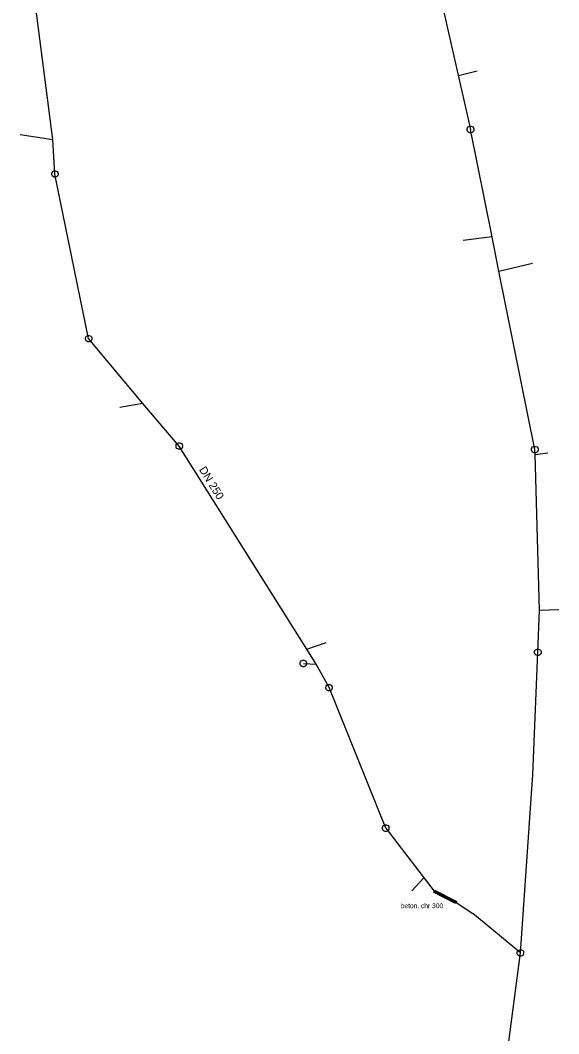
# Model space of a CAD drawing. Extents: x -717256 to -716843, y -1145423 to -1142840.
# Drawn here: x -717074.8 to -716990.8, y -1143505.2 to -1143346.8 of the extents above; entities that cross this region are included whole.
import ezdxf

# ---------------------------------------------------------------- set-up
doc = ezdxf.new("R2010")
doc.units = 0
for name, color, linetype in [('Vrstva 29', 7, 'Continuous'), ('Vrstva 30', 7, 'Continuous'), ('Vrstva 31', 7, 'Continuous')]:
    doc.layers.add(name, color=color, linetype=linetype)

msp = doc.modelspace()

# ---------------------------------------------------------------- linework, layer by layer
at = {"layer": 'Vrstva 29'}
for p, q in [((-717006.857, -1143484.87), (-717010.323, -1143483.098)), ((-717010.14, -1143482.741), (-717006.674, -1143484.513))]:
    msp.add_line(p, q, dxfattribs=at)
at = {"layer": 'Vrstva 30'}
for p, q in [((-717010.994, -1143335.446), (-717004.534, -1143363.907)), ((-717069.755, -1143365.449), (-717073.23, -1143338.352)), ((-717005.034, -1143363.807), (-717004.984, -1143363.657)), ((-717005.034, -1143364.007), (-717005.034, -1143363.807)), ((-717004.934, -1143364.257), (-717005.034, -1143364.007)), ((-717004.984, -1143363.657), (-717004.884, -1143363.507)), ((-717004.784, -1143364.357), (-717004.934, -1143364.257)), ((-717004.884, -1143363.507), (-717004.634, -1143363.407)), ((-717004.634, -1143364.407), (-717004.784, -1143364.357)), ((-717004.634, -1143363.407), (-717004.434, -1143363.407)), ((-717004.434, -1143364.407), (-717004.634, -1143364.407)), ((-717001.163, -1143380.697), (-717004.534, -1143363.907)), ((-717004.434, -1143363.407), (-717004.184, -1143363.507)), ((-717004.284, -1143364.357), (-717004.434, -1143364.407)), ((-717004.134, -1143364.257), (-717004.284, -1143364.357)), ((-717004.184, -1143363.507), (-717004.084, -1143363.657)), ((-717004.034, -1143364.007), (-717004.134, -1143364.257)), ((-717004.084, -1143363.657), (-717004.034, -1143363.807)), ((-717004.034, -1143363.807), (-717004.034, -1143364.007)), ((-717069.432, -1143370.872), (-717069.755, -1143365.449)), ((-717069.932, -1143370.772), (-717069.882, -1143370.622)), ((-717069.932, -1143370.972), (-717069.932, -1143370.772)), ((-717069.832, -1143371.222), (-717069.932, -1143370.972)), ((-717069.882, -1143370.622), (-717069.782, -1143370.472)), ((-717069.782, -1143370.472), (-717069.532, -1143370.372)), ((-717069.532, -1143370.372), (-717069.332, -1143370.372)), ((-717064.173, -1143396.576), (-717069.432, -1143370.872)), ((-717069.332, -1143370.372), (-717069.082, -1143370.472)), ((-717069.082, -1143370.472), (-717068.982, -1143370.622)), ((-717068.932, -1143370.972), (-717069.032, -1143371.222)), ((-717068.982, -1143370.622), (-717068.932, -1143370.772)), ((-717068.932, -1143370.772), (-717068.932, -1143370.972)), ((-717069.682, -1143371.322), (-717069.832, -1143371.222)), ((-717069.532, -1143371.372), (-717069.682, -1143371.322)), ((-717069.332, -1143371.372), (-717069.532, -1143371.372)), ((-717069.182, -1143371.322), (-717069.332, -1143371.372)), ((-717069.032, -1143371.222), (-717069.182, -1143371.322)), ((-717000.094, -1143386.019), (-717001.163, -1143380.697)), ((-716994.495, -1143413.916), (-717000.094, -1143386.019)), ((-717064.673, -1143396.476), (-717064.623, -1143396.326)), ((-717064.623, -1143396.326), (-717064.523, -1143396.176)), ((-717064.523, -1143396.176), (-717064.273, -1143396.076)), ((-717064.273, -1143396.076), (-717064.073, -1143396.076)), ((-717064.073, -1143396.076), (-717063.823, -1143396.176)), ((-717063.823, -1143396.176), (-717063.723, -1143396.326)), ((-717063.723, -1143396.326), (-717063.673, -1143396.476)), ((-717064.673, -1143396.676), (-717064.673, -1143396.476)), ((-717064.573, -1143396.926), (-717064.673, -1143396.676)), ((-717064.423, -1143397.026), (-717064.573, -1143396.926)), ((-717064.273, -1143397.076), (-717064.423, -1143397.026)), ((-717064.073, -1143397.076), (-717064.273, -1143397.076)), ((-717055.701, -1143406.717), (-717064.173, -1143396.576)), ((-717063.923, -1143397.026), (-717064.073, -1143397.076)), ((-717063.773, -1143396.926), (-717063.923, -1143397.026)), ((-717063.673, -1143396.676), (-717063.773, -1143396.926)), ((-717063.673, -1143396.476), (-717063.673, -1143396.676)), ((-717050.027, -1143413.377), (-717055.701, -1143406.717)), ((-717050.527, -1143413.277), (-717050.477, -1143413.127)), ((-717050.527, -1143413.477), (-717050.527, -1143413.277)), ((-717050.427, -1143413.727), (-717050.527, -1143413.477)), ((-717050.477, -1143413.127), (-717050.377, -1143412.977)), ((-717050.277, -1143413.827), (-717050.427, -1143413.727)), ((-717050.377, -1143412.977), (-717050.127, -1143412.877)), ((-717050.127, -1143413.877), (-717050.277, -1143413.827)), ((-717050.127, -1143412.877), (-717049.927, -1143412.877)), ((-717030.074, -1143445.109), (-717050.027, -1143413.377)), ((-717049.927, -1143412.877), (-717049.677, -1143412.977)), ((-717049.777, -1143413.827), (-717049.927, -1143413.877)), ((-717049.627, -1143413.727), (-717049.777, -1143413.827)), ((-717049.677, -1143412.977), (-717049.577, -1143413.127)), ((-717049.527, -1143413.477), (-717049.627, -1143413.727)), ((-717049.577, -1143413.127), (-717049.527, -1143413.277)), ((-717049.527, -1143413.277), (-717049.527, -1143413.477)), ((-716994.995, -1143413.816), (-716994.945, -1143413.666)), ((-716994.995, -1143414.016), (-716994.995, -1143413.816)), ((-716994.945, -1143413.666), (-716994.845, -1143413.516)), ((-716994.845, -1143413.516), (-716994.595, -1143413.416)), ((-716994.595, -1143413.416), (-716994.395, -1143413.416)), ((-716994.395, -1143413.416), (-716994.145, -1143413.516)), ((-716994.145, -1143413.516), (-716994.045, -1143413.666)), ((-716994.045, -1143413.666), (-716993.995, -1143413.816)), ((-716993.995, -1143413.816), (-716993.995, -1143414.016)), ((-717049.927, -1143413.877), (-717050.127, -1143413.877)), ((-716994.895, -1143414.266), (-716994.995, -1143414.016)), ((-716994.745, -1143414.366), (-716994.895, -1143414.266)), ((-716994.595, -1143414.416), (-716994.745, -1143414.366)), ((-716994.395, -1143414.416), (-716994.595, -1143414.416)), ((-716994.445, -1143414.701), (-716994.495, -1143413.916)), ((-716993.761, -1143438.992), (-716994.445, -1143414.701)), ((-716994.245, -1143414.366), (-716994.395, -1143414.416)), ((-716994.095, -1143414.266), (-716994.245, -1143414.366)), ((-716993.995, -1143414.016), (-716994.095, -1143414.266)), ((-716994.028, -1143445.588), (-716993.761, -1143438.992)), ((-717028.617, -1143447.427), (-717030.074, -1143445.109)), ((-716994.528, -1143445.488), (-716994.478, -1143445.338)), ((-716994.528, -1143445.688), (-716994.528, -1143445.488)), ((-716994.478, -1143445.338), (-716994.378, -1143445.188)), ((-716994.378, -1143445.188), (-716994.128, -1143445.088)), ((-716994.128, -1143445.088), (-716993.928, -1143445.088)), ((-716993.928, -1143445.088), (-716993.678, -1143445.188)), ((-716993.678, -1143445.188), (-716993.578, -1143445.338)), ((-716993.578, -1143445.338), (-716993.528, -1143445.488)), ((-716993.528, -1143445.488), (-716993.528, -1143445.688)), ((-716994.806, -1143464.667), (-716994.028, -1143445.588)), ((-716994.428, -1143445.938), (-716994.528, -1143445.688)), ((-716994.278, -1143446.038), (-716994.428, -1143445.938)), ((-716994.128, -1143446.088), (-716994.278, -1143446.038)), ((-716993.928, -1143446.088), (-716994.128, -1143446.088)), ((-716993.778, -1143446.038), (-716993.928, -1143446.088)), ((-716993.628, -1143445.938), (-716993.778, -1143446.038)), ((-716993.528, -1143445.688), (-716993.628, -1143445.938)), ((-717026.624, -1143451.112), (-717028.617, -1143447.427)), ((-717027.124, -1143451.012), (-717027.074, -1143450.862)), ((-717027.124, -1143451.212), (-717027.124, -1143451.012)), ((-717027.024, -1143451.462), (-717027.124, -1143451.212)), ((-717027.074, -1143450.862), (-717026.974, -1143450.712)), ((-717026.874, -1143451.562), (-717027.024, -1143451.462)), ((-717026.974, -1143450.712), (-717026.724, -1143450.612)), ((-717026.724, -1143451.612), (-717026.874, -1143451.562)), ((-717026.724, -1143450.612), (-717026.524, -1143450.612)), ((-717026.524, -1143451.612), (-717026.724, -1143451.612)), ((-717017.766, -1143473.08), (-717026.624, -1143451.112)), ((-717026.524, -1143450.612), (-717026.274, -1143450.712)), ((-717026.374, -1143451.562), (-717026.524, -1143451.612)), ((-717026.224, -1143451.462), (-717026.374, -1143451.562)), ((-717026.274, -1143450.712), (-717026.174, -1143450.862)), ((-717026.124, -1143451.212), (-717026.224, -1143451.462)), ((-717026.174, -1143450.862), (-717026.124, -1143451.012)), ((-717026.124, -1143451.012), (-717026.124, -1143451.212)), ((-716996.737, -1143492.566), (-716994.806, -1143464.667)), ((-717018.266, -1143472.98), (-717018.216, -1143472.83)), ((-717018.266, -1143473.18), (-717018.266, -1143472.98)), ((-717018.166, -1143473.43), (-717018.266, -1143473.18)), ((-717018.216, -1143472.83), (-717018.116, -1143472.68)), ((-717018.016, -1143473.53), (-717018.166, -1143473.43)), ((-717018.116, -1143472.68), (-717017.866, -1143472.58)), ((-717017.866, -1143473.58), (-717018.016, -1143473.53)), ((-717017.866, -1143472.58), (-717017.666, -1143472.58)), ((-717017.666, -1143473.58), (-717017.866, -1143473.58)), ((-717017.766, -1143473.08), (-717010.232, -1143482.92)), ((-717017.666, -1143472.58), (-717017.416, -1143472.68)), ((-717017.516, -1143473.53), (-717017.666, -1143473.58)), ((-717017.366, -1143473.43), (-717017.516, -1143473.53)), ((-717017.416, -1143472.68), (-717017.316, -1143472.83)), ((-717017.266, -1143473.18), (-717017.366, -1143473.43)), ((-717017.316, -1143472.83), (-717017.266, -1143472.98)), ((-717017.266, -1143472.98), (-717017.266, -1143473.18)), ((-717010.232, -1143482.92), (-717006.766, -1143484.692)), ((-717006.766, -1143484.692), (-717004.196, -1143486.392)), ((-716996.737, -1143492.566), (-717004.196, -1143486.392)), ((-717000.334, -1143519.778), (-716996.737, -1143492.566)), ((-716997.237, -1143492.466), (-716997.187, -1143492.316)), ((-716997.237, -1143492.666), (-716997.237, -1143492.466)), ((-716997.137, -1143492.916), (-716997.237, -1143492.666)), ((-716997.187, -1143492.316), (-716997.087, -1143492.166)), ((-716996.987, -1143493.016), (-716997.137, -1143492.916)), ((-716997.087, -1143492.166), (-716996.837, -1143492.066)), ((-716996.837, -1143493.066), (-716996.987, -1143493.016)), ((-716996.837, -1143492.066), (-716996.637, -1143492.066)), ((-716996.637, -1143492.066), (-716996.387, -1143492.166)), ((-716996.487, -1143493.016), (-716996.637, -1143493.066)), ((-716996.337, -1143492.916), (-716996.487, -1143493.016)), ((-716996.387, -1143492.166), (-716996.287, -1143492.316)), ((-716996.237, -1143492.666), (-716996.337, -1143492.916)), ((-716996.287, -1143492.316), (-716996.237, -1143492.466)), ((-716996.237, -1143492.466), (-716996.237, -1143492.666)), ((-716996.637, -1143493.066), (-716996.837, -1143493.066))]:
    msp.add_line(p, q, dxfattribs=at)
at = {"layer": 'Vrstva 31'}
for p, q in [((-717006.419, -1143355.46), (-717003.489, -1143354.74)), ((-717074.847, -1143364.697), (-717069.755, -1143365.449)), ((-717001.163, -1143380.697), (-717005.659, -1143381.249)), ((-717000.094, -1143386.019), (-716994.866, -1143384.794)), ((-717055.701, -1143406.717), (-717059.29, -1143407.323)), ((-716994.445, -1143414.701), (-716992.436, -1143414.452)), ((-716993.761, -1143438.992), (-716990.761, -1143438.912)), ((-717030.074, -1143445.109), (-717027.092, -1143444.073)), ((-717031.14, -1143447.245), (-717031.09, -1143447.095)), ((-717031.09, -1143447.095), (-717030.99, -1143446.945)), ((-717030.99, -1143446.945), (-717030.74, -1143446.845)), ((-717030.74, -1143446.845), (-717030.54, -1143446.845)), ((-717030.54, -1143446.845), (-717030.29, -1143446.945)), ((-717030.29, -1143446.945), (-717030.19, -1143447.095)), ((-717030.19, -1143447.095), (-717030.14, -1143447.245)), ((-717031.14, -1143447.445), (-717031.14, -1143447.245)), ((-717031.04, -1143447.695), (-717031.14, -1143447.445)), ((-717030.89, -1143447.795), (-717031.04, -1143447.695)), ((-717030.74, -1143447.845), (-717030.89, -1143447.795)), ((-717030.54, -1143447.845), (-717030.74, -1143447.845)), ((-717030.64, -1143447.345), (-717028.617, -1143447.427)), ((-717030.39, -1143447.795), (-717030.54, -1143447.845)), ((-717030.24, -1143447.695), (-717030.39, -1143447.795)), ((-717030.14, -1143447.445), (-717030.24, -1143447.695)), ((-717030.14, -1143447.245), (-717030.14, -1143447.445)), ((-717011.824, -1143480.839), (-717013.713, -1143482.861))]:
    msp.add_line(p, q, dxfattribs=at)

# ---------------------------------------------------------------- texts
at = {"layer": 'Vrstva 30'}
msp.add_text('DN 250', height=1.25, rotation=301.5, dxfattribs=at).set_placement((-717046.98, -1143417.041))
msp.add_text('beton. chr 300', height=0.74999, dxfattribs=at).set_placement((-717015.432, -1143485.576))

doc.saveas('drawing.dxf')
